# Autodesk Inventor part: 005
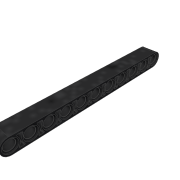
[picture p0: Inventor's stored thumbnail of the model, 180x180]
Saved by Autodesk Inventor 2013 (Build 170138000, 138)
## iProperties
Created: 2013-03
Part Number: 005
Material: Generic
Document SubType Name: Modeling
Designer: perblt
Density: 1 g/cm^3
Author: perblt
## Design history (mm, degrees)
sketch "Sketch2" dims "d10" = 10, "d95" = 10
  geometry: L1 (-69.6, 0)-(53.6, 0) reference; L2 (32, -4)-(0, -4); L3 (4, 4)-(32, 4); L4 (-4, -4)-(-4, -3.79); L5 (0, -4)-(-48, -4); L6 (3.2, 4)-(-48, 4); L7 (4, 4)-(3.2, 4); C1 r 3.2 at (0, 0); C2 r 3.2 at (8, 0); C3 r 3.2 at (16, 0); C4 r 3.2 at (24, 0); C5 r 3.2 at (32, 0); C6 r 3.2 at (-8, 0); C7 r 3.2 at (-16, 0); C8 r 3.2 at (-24, 0); C9 r 3.2 at (-32, 0); C10 r 3.2 at (-40, 0); C11 r 3.2 at (-48, 0); A1 r 4 centre (32, 0) between (32, -4) and (32, 4); A2 r 4 centre (-48, 0) between (-48, 4) and (-48, -4); 1 further point
  constraints: 13 centre point, 12 end point, 4 point on circle, 3 coincident, 3 horizontal, 2 parallel, 2 tangent, 1 collinear, 20 other
  dimensions: "d" = 6.4 diameter of C1; "d7" = 8 distance of C1.centre C2.centre; "d22" = 8 distance between parallel lines of L3 L2; "d24" = 4 radius of A1; "d92" = 8 distance of C1.centre C6.centre; "d97" = 8 diameter of A2
extrude "Extrusion6" new body sketch "Sketch2" stored distance "d98" = 8; taper "d99" = 0 deg
sketch "Sketch4"
  geometry: L1 (32, -4)-(0, -4); L2 (28.83, -3)-(27.17, -3); L3 (27.17, 3)-(28.83, 3); L4 (20.83, -3)-(19.17, -3); L5 (19.17, 3)-(20.83, 3); L6 (12.83, -3)-(11.17, -3); L7 (11.17, 3)-(12.83, 3); L8 (4.83, -3)-(3.17, -3); L9 (3.17, 3)-(4.83, 3); L10 (-3.17, -3)-(-4.83, -3); L11 (-4.83, 3)-(-3.17, 3); L12 (-11.17, -3)-(-12.83, -3); L13 (-12.83, 3)-(-11.17, 3); L14 (-19.17, -3)-(-20.83, -3); L15 (-20.83, 3)-(-19.17, 3); L16 (-27.17, -3)-(-28.83, -3); L17 (-28.83, 3)-(-27.17, 3); L18 (-35.17, -3)-(-36.83, -3); L19 (-36.83, 3)-(-35.17, 3); L20 (-43.17, -3)-(-44.83, -3); L21 (-44.83, 3)-(-43.17, 3); A1 r 3.7 centre (32, 0) between (29.139, 2.346) and (29.139, -2.346); A2 r 3.7 centre (24, 0) between (26.861, -2.346) and (26.861, 2.346); A3 r 0.4 centre (27.17, -2.6) between (26.861, -2.346) and (27.17, -3); A4 r 0.4 centre (28.83, -2.6) between (28.83, -3) and (29.139, -2.346); A5 r 0.4 centre (27.17, 2.6) between (27.17, 3) and (26.861, 2.346); A6 r 0.4 centre (28.83, 2.6) between (29.139, 2.346) and (28.83, 3); A7 r 0.4 centre (20.83, -2.6) between (20.83, -3) and (21.139, -2.346); A8 r 0.4 centre (19.17, -2.6) between (18.861, -2.346) and (19.17, -3); A9 r 3.7 centre (24, 0) between (21.139, 2.346) and (21.139, -2.346); A10 r 3.7 centre (16, 0) between (18.861, -2.346) and (18.861, 2.346); A11 r 0.4 centre (20.83, 2.6) between (21.139, 2.346) and (20.83, 3); A12 r 0.4 centre (19.17, 2.6) between (19.17, 3) and (18.861, 2.346); A13 r 0.4 centre (12.83, -2.6) between (12.83, -3) and (13.139, -2.346); A14 r 0.4 centre (11.17, -2.6) between (10.861, -2.346) and (11.17, -3); A15 r 3.7 centre (16, 0) between (13.139, 2.346) and (13.139, -2.346); A16 r 3.7 centre (8, 0) between (10.861, -2.346) and (10.861, 2.346); A17 r 0.4 centre (12.83, 2.6) between (13.139, 2.346) and (12.83, 3); A18 r 0.4 centre (11.17, 2.6) between (11.17, 3) and (10.861, 2.346); A19 r 0.4 centre (4.83, -2.6) between (4.83, -3) and (5.139, -2.346); A20 r 0.4 centre (3.17, -2.6) between (2.861, -2.346) and (3.17, -3); A21 r 3.7 centre (8, 0) between (5.139, 2.346) and (5.139, -2.346); A22 r 3.7 centre (0, 0) between (2.861, -2.346) and (2.861, 2.346); A23 r 0.4 centre (4.83, 2.6) between (5.139, 2.346) and (4.83, 3); A24 r 0.4 centre (3.17, 2.6) between (3.17, 3) and (2.861, 2.346); A25 r 0.4 centre (-3.17, -2.6) between (-3.17, -3) and (-2.861, -2.346); A26 r 0.4 centre (-4.83, -2.6) between (-5.139, -2.346) and (-4.83, -3); A27 r 3.7 centre (0, 0) between (-2.861, 2.346) and (-2.861, -2.346); A28 r 3.7 centre (-8, 0) between (-5.139, -2.346) and (-5.139, 2.346); A29 r 0.4 centre (-3.17, 2.6) between (-2.861, 2.346) and (-3.17, 3); A30 r 0.4 centre (-4.83, 2.6) between (-4.83, 3) and (-5.139, 2.346); A31 r 0.4 centre (-11.17, -2.6) between (-11.17, -3) and (-10.861, -2.346); A32 r 0.4 centre (-12.83, -2.6) between (-13.139, -2.346) and (-12.83, -3); A33 r 3.7 centre (-8, 0) between (-10.861, 2.346) and (-10.861, -2.346); A34 r 3.7 centre (-16, 0) between (-13.139, -2.346) and (-13.139, 2.346); A35 r 0.4 centre (-11.17, 2.6) between (-10.861, 2.346) and (-11.17, 3); A36 r 0.4 centre (-12.83, 2.6) between (-12.83, 3) and (-13.139, 2.346); A37 r 0.4 centre (-19.17, -2.6) between (-19.17, -3) and (-18.861, -2.346); A38 r 0.4 centre (-20.83, -2.6) between (-21.139, -2.346) and (-20.83, -3); A39 r 3.7 centre (-16, 0) between (-18.861, 2.346) and (-18.861, -2.346); A40 r 3.7 centre (-24, 0) between (-21.139, -2.346) and (-21.139, 2.346); A41 r 0.4 centre (-19.17, 2.6) between (-18.861, 2.346) and (-19.17, 3); A42 r 0.4 centre (-20.83, 2.6) between (-20.83, 3) and (-21.139, 2.346); A43 r 0.4 centre (-27.17, -2.6) between (-27.17, -3) and (-26.861, -2.346); A44 r 0.4 centre (-28.83, -2.6) between (-29.139, -2.346) and (-28.83, -3); A45 r 3.7 centre (-24, 0) between (-26.861, 2.346) and (-26.861, -2.346); A46 r 3.7 centre (-32, 0) between (-29.139, -2.346) and (-29.139, 2.346); A47 r 0.4 centre (-27.17, 2.6) between (-26.861, 2.346) and (-27.17, 3); A48 r 0.4 centre (-28.83, 2.6) between (-28.83, 3) and (-29.139, 2.346); A49 r 0.4 centre (-35.17, -2.6) between (-35.17, -3) and (-34.861, -2.346); A50 r 0.4 centre (-36.83, -2.6) between (-37.139, -2.346) and (-36.83, -3); A51 r 3.7 centre (-32, 0) between (-34.861, 2.346) and (-34.861, -2.346); A52 r 3.7 centre (-40, 0) between (-37.139, -2.346) and (-37.139, 2.346); A53 r 0.4 centre (-35.17, 2.6) between (-34.861, 2.346) and (-35.17, 3); A54 r 0.4 centre (-36.83, 2.6) between (-36.83, 3) and (-37.139, 2.346); A55 r 0.4 centre (-43.17, -2.6) between (-43.17, -3) and (-42.861, -2.346); A56 r 0.4 centre (-44.83, -2.6) between (-45.139, -2.346) and (-44.83, -3); A57 r 3.7 centre (-40, 0) between (-42.861, 2.346) and (-42.861, -2.346); A58 r 3.7 centre (-48, 0) between (-45.139, -2.346) and (-45.139, 2.346); A59 r 0.4 centre (-43.17, 2.6) between (-42.861, 2.346) and (-43.17, 3); A60 r 0.4 centre (-44.83, 2.6) between (-44.83, 3) and (-45.139, 2.346); 1 further point
  constraints: 120 point on circle, 60 centre point, 42 end point, 8 tangent, 1 horizontal, 1 parallel, 198 other
  dimensions: "d45" = 7.4 diameter of A1; "d46" = 7.4 diameter of A2; "d49" = 0.8 diameter of A3; "d50" = 0.8 diameter of A4; "d51" = 0.8 diameter of A5; "d52" = 0.8 diameter of A6; "d57" = 8 distance of A1.end A7.end
extrude "Extrusion8" cut sketch "Sketch4" stored distance "d120" = 50; taper "d121" = 0 deg
sketch "Sketch3" dims "d41" = 10, "d105" = 10
  geometry: L1 (0, -4.752)-(0, 4.752) reference; L2 (-68.752, 0)-(52.752, 0) reference; C1 r 2.4 at (0, 0); C2 r 3.394 at (0, 0); C3 r 2.4 at (8, 0); C4 r 3.394 at (8, 0); C5 r 2.4 at (16, 0); C6 r 3.394 at (16, 0); C7 r 2.4 at (24, 0); C8 r 3.394 at (24, 0); C9 r 2.4 at (32, 0); C10 r 3.394 at (32, 0); C11 r 2.4 at (-8, 0); C12 r 3.394 at (-8, 0); C13 r 2.4 at (-16, 0); C14 r 3.394 at (-16, 0); C15 r 2.4 at (-24, 0); C16 r 3.394 at (-24, 0); C17 r 2.4 at (-32, 0); C18 r 3.394 at (-32, 0); C19 r 2.4 at (-40, 0); C20 r 3.394 at (-40, 0); C21 r 2.4 at (-48, 0); C22 r 3.394 at (-48, 0); 7 further points
  constraints: 22 centre point, 18 coincident, 2 horizontal, 46 other
  dimensions: "d28" = 4.8 diameter of C1; "d38" = 8 distance of C1.centre C3.centre; "d102" = 8 distance of point (0, 0) point (-8, 0)
extrude "Extrusion2" new body sketch "Sketch3" stored distance "d43" = 6.4; taper "d44" = 0 deg
sketch "Sketch5" dims "d82" = 10
  geometry: L1 (26.635, 3.313)-(29.368, 3.313); L2 (29.368, 3.313)-(29.368, -3.607); L3 (29.368, -3.607)-(26.635, -3.607); L4 (26.635, -3.607)-(26.635, 3.313); L5 (4, 4)-(32, 4); L6 (18.635, 3.313)-(21.368, 3.313); L7 (21.368, 3.313)-(21.368, -3.607); L8 (21.368, -3.607)-(18.635, -3.607); L9 (18.635, -3.607)-(18.635, 3.313); L10 (10.635, 3.313)-(13.368, 3.313); L11 (13.368, 3.313)-(13.368, -3.607); L12 (13.368, -3.607)-(10.635, -3.607); L13 (10.635, -3.607)-(10.635, 3.313); L14 (2.635, 3.313)-(5.368, 3.313); L15 (5.368, 3.313)-(5.368, -3.607); L16 (5.368, -3.607)-(2.635, -3.607); L17 (2.635, -3.607)-(2.635, 3.313); L18 (-5.365, 3.313)-(-2.632, 3.313); L19 (-2.632, 3.313)-(-2.632, -3.607); L20 (-2.632, -3.607)-(-5.365, -3.607); L21 (-5.365, -3.607)-(-5.365, 3.313); L22 (-13.365, 3.313)-(-10.632, 3.313); L23 (-10.632, 3.313)-(-10.632, -3.607); L24 (-10.632, -3.607)-(-13.365, -3.607); L25 (-13.365, -3.607)-(-13.365, 3.313); L26 (-21.365, 3.313)-(-18.632, 3.313); L27 (-18.632, 3.313)-(-18.632, -3.607); L28 (-18.632, -3.607)-(-21.365, -3.607); L29 (-21.365, -3.607)-(-21.365, 3.313); L30 (-29.365, 3.313)-(-26.632, 3.313); L31 (-26.632, 3.313)-(-26.632, -3.607); L32 (-26.632, -3.607)-(-29.365, -3.607); L33 (-29.365, -3.607)-(-29.365, 3.313); L34 (-37.365, 3.313)-(-34.632, 3.313); L35 (-34.632, 3.313)-(-34.632, -3.607); L36 (-34.632, -3.607)-(-37.365, -3.607); L37 (-37.365, -3.607)-(-37.365, 3.313); L38 (-45.365, 3.313)-(-42.632, 3.313); L39 (-42.632, 3.313)-(-42.632, -3.607); L40 (-42.632, -3.607)-(-45.365, -3.607); L41 (-45.365, -3.607)-(-45.365, 3.313)
  constraints: 82 end point, 2 horizontal, 2 parallel, 1 perpendicular, 72 other
  dimensions: "d79" = 8 distance of L1.start L6.start
extrude "Extrusion4" join sketch "Sketch5" stored distance "d84" = 1.6; taper "d85" = 0 deg
fillet "Fillet1" dims "d122" = 0.1
body "Solid1"
body "Solid2"
other parameters: "d0" = 4.8, "d47" = 1, "d48" = 1, "d63" = 7.4, "d64" = 1, "d65" = 1
